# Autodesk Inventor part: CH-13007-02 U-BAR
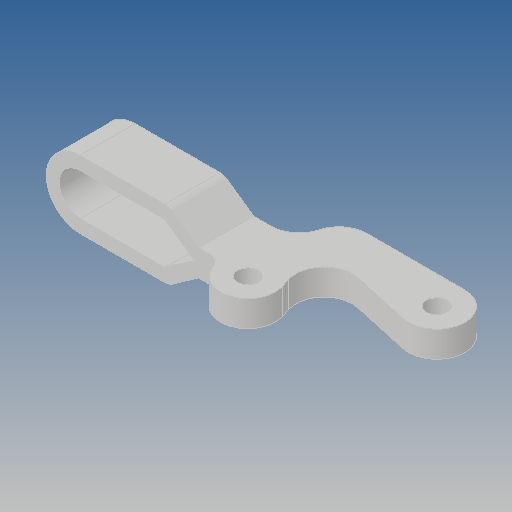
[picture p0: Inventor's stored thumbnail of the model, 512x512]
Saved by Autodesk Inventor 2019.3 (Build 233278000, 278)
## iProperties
Created: 2017-11
Part Number: CH-13007-02 U-BAR
Material: Ogólny
Document SubType Name: Modeling
Designer: Admin
Density: 1 g/cm^3
Appearance: Domyślna
Author: Admin
Revision Number: ÈÎºÎ
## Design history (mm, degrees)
feature "ÇÐ³ý-À­Éì2"
node "Bryła1"
